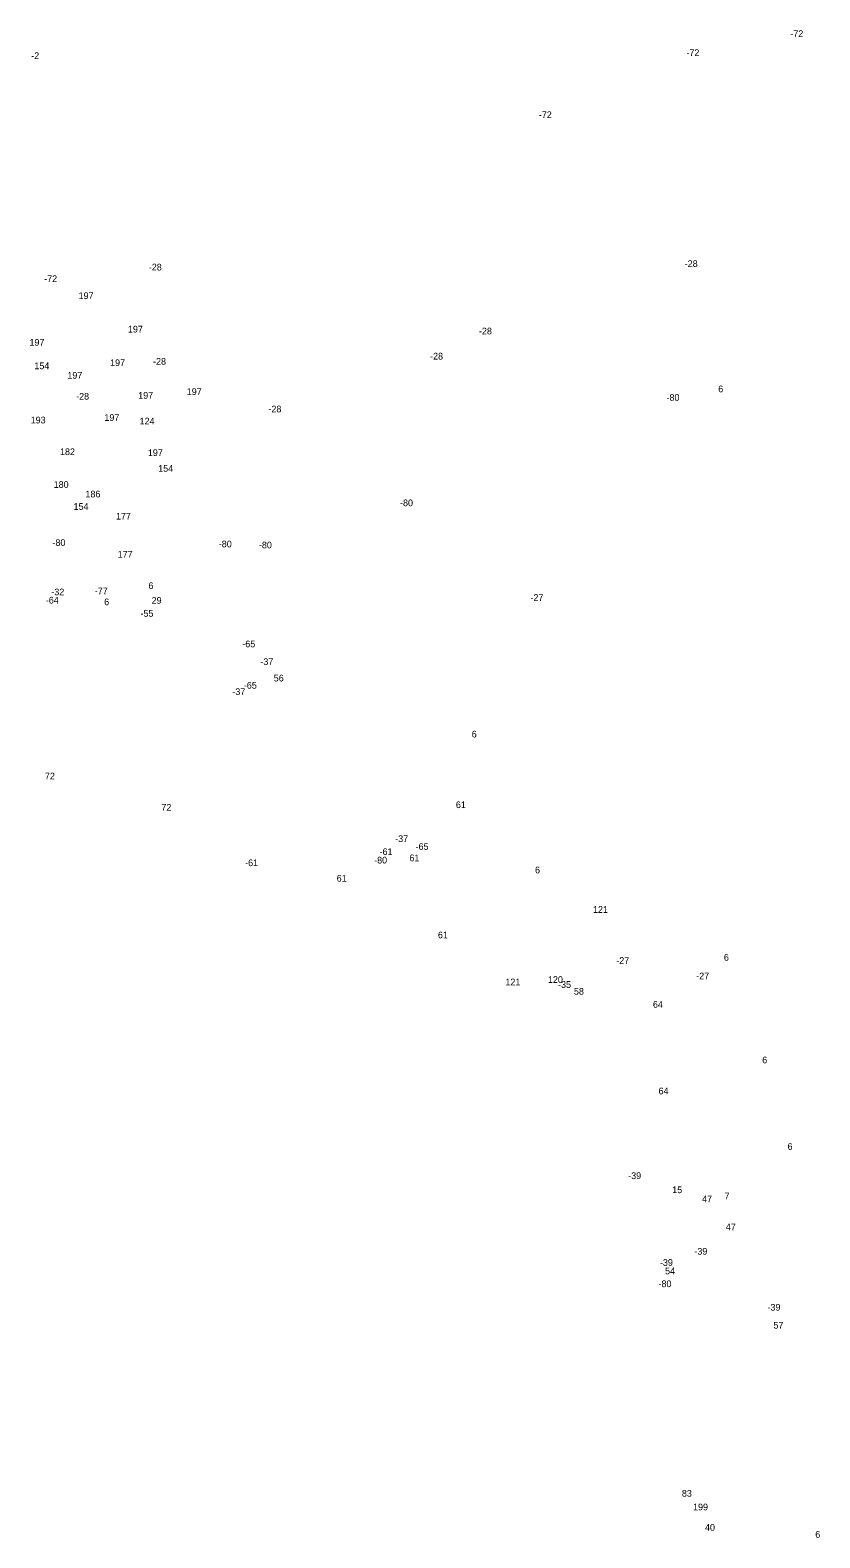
# Model space of a CAD drawing. Extents: x -664022 to -660357, y -995564 to -992665.
# Drawn here: x -661780 to -661309, y -994749 to -993850 of the extents above; entities that cross this region are included whole.
import ezdxf

# ---------------------------------------------------------------- set-up
doc = ezdxf.new("R2010")
doc.units = 0
doc.layers.add('Vrstva 24', color=7, linetype='Continuous')

msp = doc.modelspace()

# ---------------------------------------------------------------- texts
at = {"layer": 'Vrstva 24'}
for s, p in [('-72', (-661326.812, -993853.62)), ('-2', (-661779.806, -993866.81)), ('-72', (-661388.802, -993864.96)), ('-72', (-661476.892, -993902.03)), ('-28', (-661709.636, -993992.97)), ('-28', (-661389.826, -993990.87)), ('-72', (-661772.072, -993999.88)), ('197', (-661751.533, -994010.05)), ('197', (-661722.093, -994029.99)), ('-28', (-661512.616, -994031.12)), ('197', (-661780.853, -994037.88)), ('154', (-661777.926, -994051.88)), ('197', (-661732.753, -994050.01)), ('-28', (-661707.106, -994049.22)), ('-28', (-661541.786, -994046.11)), ('197', (-661758.253, -994057.58)), ('-28', (-661753.006, -994070.05)), ('197', (-661715.953, -994069.49)), ('197', (-661687.013, -994067.3)), ('-80', (-661400.71, -994070.75)), ('6', (-661369.834, -994065.66)), ('-28', (-661638.256, -994077.64)), ('193', (-661780.138, -994084.25)), ('197', (-661736.153, -994082.72)), ('124', (-661715.146, -994084.84)), ('182', (-661762.642, -994103.15)), ('197', (-661710.193, -994103.7)), ('154', (-661704.016, -994113.07)), ('180', (-661766.416, -994122.7)), ('186', (-661747.448, -994128.39)), ('-80', (-661559.72, -994133.65)), ('154', (-661754.566, -994135.81)), ('177', (-661729.223, -994141.61)), ('-80', (-661767.15, -994157.37)), ('-80', (-661667.88, -994158.18)), ('-80', (-661643.93, -994158.78)), ('177', (-661728.213, -994164.29)), ('-32', (-661767.806, -994186.79)), ('-32', (-661767.806, -994186.79)), ('-77', (-661741.866, -994186.16)), ('6', (-661709.834, -994183.07)), ('-64', (-661771.106, -994191.73)), ('6', (-661736.274, -994192.73)), ('6', (-661736.274, -994192.73)), ('29', (-661707.954, -994191.85)), ('-27', (-661481.892, -994190.17)), ('-55', (-661714.616, -994199.61)), ('-65', (-661653.851, -994217.82)), ('-37', (-661643.082, -994228.4)), ('-65', (-661652.931, -994242.54)), ('56', (-661635.074, -994238.22)), ('-37', (-661659.802, -994246.31)), ('6', (-661516.944, -994271.66)), ('72', (-661771.634, -994296.68)), ('61', (-661526.388, -994313.79)), ('72', (-661702.164, -994315.37)), ('-37', (-661562.612, -994334.03)), ('-65', (-661550.451, -994338.73)), ('-61', (-661652.155, -994348.43)), ('-80', (-661575.18, -994346.85)), ('-61', (-661571.935, -994341.8)), ('61', (-661554.098, -994345.5)), ('61', (-661597.538, -994357.68)), ('6', (-661479.164, -994352.71)), ('121', (-661444.586, -994376.31)), ('61', (-661537.098, -994391.48)), ('-27', (-661430.692, -994406.77)), ('6', (-661366.454, -994404.91)), ('121', (-661496.846, -994419.56)), ('120', (-661471.456, -994418.1)), ('-35', (-661465.396, -994421.07)), ('-27', (-661382.962, -994415.98)), ('58', (-661455.938, -994425.14)), ('64', (-661408.808, -994432.95)), ('6', (-661343.574, -994466.1)), ('64', (-661405.448, -994484.61)), ('6', (-661328.464, -994517.76)), ('-39', (-661423.571, -994535.14)), ('15', (-661397.282, -994543.57)), ('7', (-661366.054, -994547.25)), ('47', (-661379.478, -994549.03)), ('47', (-661365.308, -994565.73)), ('-39', (-661384.081, -994580.27)), ('-39', (-661404.621, -994586.96)), ('54', (-661401.542, -994592.03)), ('-80', (-661405.49, -994599.66)), ('-39', (-661340.431, -994613.68)), ('57', (-661336.904, -994624.41)), ('83', (-661391.538, -994724.71)), ('199', (-661384.863, -994732.88)), ('40', (-661377.726, -994745.05)), ('6', (-661311.934, -994749.21))]:
    msp.add_text(s, height=4, dxfattribs=at).set_placement(p)

doc.saveas('drawing.dxf')
